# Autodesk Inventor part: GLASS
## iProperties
Created: 2018-12
Part Number: GLASS
Document SubType Name: Modeling
Designer: Harindersingh
Density: 1 g/cm^3
Author: Harindersingh
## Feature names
1. Extrusion1
